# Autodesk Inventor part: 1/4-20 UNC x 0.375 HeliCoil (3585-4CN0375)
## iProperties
Title: 1/4-20 UNC x 0.375 HeliCoil (3585-4CN0375)
Author: CFitzwater
Shininess: 64.0
Angle Display Precision: 2
Document Length Units: 11272
Document Angle Units: 11286
Document Time Units: 11279
Document Mass Units: 11290
Document Length Units Precision: 3
Document Angle Units Precision: 2
Compacted: True
PropertySet Name: _Private Model Information
Created: 2002-02
Part Number: Helicoil-3585-CN
Material: Stainless Steel, Austenitic
Document SubType Name: Modeling
Designer: CFitzwater
Control State: 0
Master: False
Checked Out: False
PropertySet Name: Design Tracking Control
Density: 7.750000000000001
Volumn: 0.37239295650448834
Area: 5.5389113408432396
PropertySet Name: Model Information
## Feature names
1. Extrusion1
2. Chamfer1
3. Chamfer2
